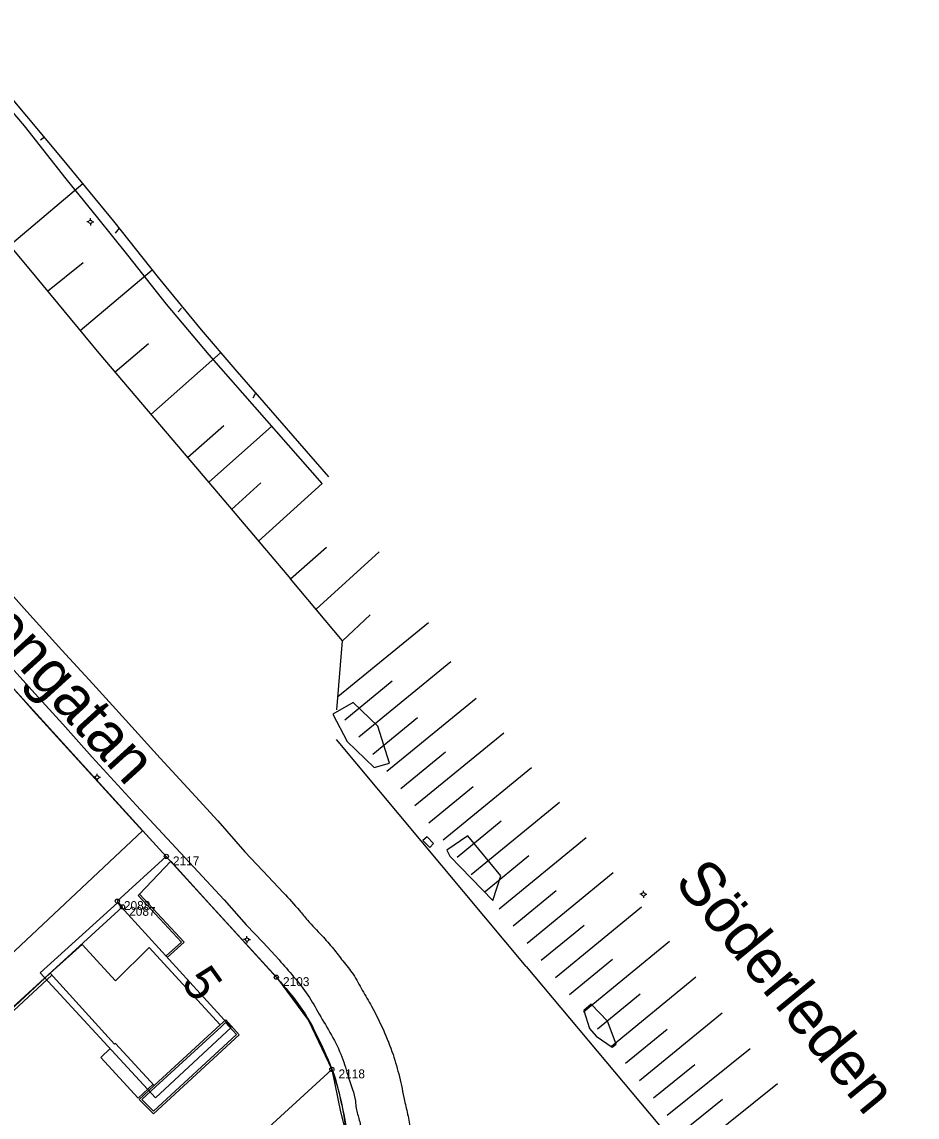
# Model space of a CAD drawing. Extents: x 1517478 to 1518189, y 6494860 to 6495389.
# Drawn here: x 1518083.7 to 1518184.6, y 6495107.4 to 6495230.8 of the extents above; entities that cross this region are included whole.
import ezdxf

# ---------------------------------------------------------------- set-up
doc = ezdxf.new("R2010")
doc.units = 0
for name, color, linetype in [('adress', 7, 'Continuous'), ('bostadshus', 7, 'Continuous'), ('gatunamn', 7, 'Continuous'), ('gc_vag', 7, 'Continuous'), ('grans', 7, 'Continuous'), ('granspunkt', 7, 'Continuous'), ('granspunkt_text', 7, 'Continuous'), ('kvartersgrans', 7, 'Continuous'), ('kvartersgrans_utan_fastgr', 7, 'Continuous'), ('kvartersytor', 7, 'Continuous'), ('planteringskant', 7, 'Continuous'), ('skarmtak', 7, 'Continuous'), ('slant_skraffering', 7, 'Continuous'), ('slantfot', 7, 'Continuous'), ('slantkron', 7, 'Continuous'), ('staket', 7, 'Continuous'), ('stenmur', 7, 'Continuous'), ('stolpe_belysning', 7, 'Continuous'), ('trappa_byggnad', 7, 'Continuous'), ('vagkant', 7, 'Continuous')]:
    doc.layers.add(name, color=color, linetype=linetype)

msp = doc.modelspace()

# ---------------------------------------------------------------- linework, layer by layer
at = {"layer": 'bostadshus'}
msp.add_lwpolyline([(1518086.89, 6495123.66), (1518090.48, 6495126.91), (1518094.25, 6495122.81), (1518098.04, 6495126.57), (1518106.03, 6495117.83), (1518098.62, 6495111.02), (1518094.24, 6495115.73), (1518094.15, 6495115.66), (1518086.88, 6495123.66)], dxfattribs=at)
at = {"layer": 'gc_vag'}
for p, q in [((1518085.02, 6495153.19), (1518097.28, 6495139.69)), ((1518100.47, 6495136.3), (1518096.97, 6495132.58))]:
    msp.add_line(p, q, dxfattribs=at)
for points in [[(1518080.55, 6495158.09), (1518082.73, 6495155.72), (1518085.02, 6495153.19)], [(1518097.3, 6495139.7), (1518079.77, 6495123.29), (1518069.67, 6495123.88)], [(1518100.47, 6495136.3), (1518105.84, 6495130.34), (1518112.4, 6495123.17)]]:
    msp.add_lwpolyline(points, dxfattribs=at)
msp.add_spline([(1518112.4, 6495123.17), (1518115.62, 6495119.07), (1518117.64, 6495115.15), (1518118.65, 6495112.85), (1518119.88, 6495108.19), (1518120.44, 6495104.77), (1518120.39, 6495101.02)], degree=3, dxfattribs=at)
at = {"layer": 'grans'}
for p, q in [((1518094.45, 6495131.78), (1518099.97, 6495136.82)), ((1518099.97, 6495136.82), (1518112.38, 6495123.21)), ((1518095.04, 6495131.13), (1518094.45, 6495131.78)), ((1518079.46, 6495116.91), (1518095.04, 6495131.13)), ((1518118.64, 6495112.82), (1518097.62, 6495093.65))]:
    msp.add_line(p, q, dxfattribs=at)
msp.add_arc((1518089.46, 6495102.3), 31.02, 19.8209, 42.3652, dxfattribs=at)
at = {"layer": 'granspunkt'}
for centre in [(1518099.97, 6495136.82), (1518094.45, 6495131.78), (1518095.04, 6495131.13), (1518112.38, 6495123.21), (1518118.64, 6495112.82)]:
    msp.add_circle(centre, 0.237, dxfattribs=at)
at = {"layer": 'kvartersgrans'}
msp.add_line((1518099.97, 6495136.82), (1518112.38, 6495123.21), dxfattribs=at)
msp.add_arc((1518089.46, 6495102.3), 31.02, 19.8209, 42.3652, dxfattribs=at)
at = {"layer": 'kvartersgrans_utan_fastgr'}
msp.add_line((1518073.64, 6495165.68), (1518099.97, 6495136.82), dxfattribs=at)
msp.add_arc((1518089.47, 6495102.32), 31.01, 350.4256, 19.8012, dxfattribs=at)
at = {"layer": 'kvartersytor'}
msp.add_lwpolyline([(1518073.64, 6495165.68), (1518099.97, 6495136.82), (1518106.17, 6495130.01), (1518112.38, 6495123.21), (1518116.02, 6495118.32), (1518118.64, 6495112.82), (1518119.61, 6495108.06), (1518120.35, 6495105.08)], dxfattribs=at)
at = {"layer": 'planteringskant'}
for points in [[(1518123.4, 6495146.83), (1518125.12, 6495147.31), (1518123.83, 6495151.48), (1518121.03, 6495154.17), (1518118.74, 6495152.84), (1518120.38, 6495149.78), (1518123.4, 6495146.83)], [(1518136.79, 6495131.84), (1518137.69, 6495134.62), (1518133.96, 6495139.12), (1518131.58, 6495137.52), (1518131.95, 6495136.86), (1518136.79, 6495131.84)], [(1518129.67, 6495137.81), (1518130.1, 6495138.28), (1518129.37, 6495139.01), (1518128.91, 6495138.6), (1518129.67, 6495137.81)], [(1518148.45, 6495116.56), (1518150.25, 6495115.31), (1518150.7, 6495115.68), (1518149.7, 6495118.24), (1518147.86, 6495120.16), (1518147.03, 6495119.44), (1518147.69, 6495117.42), (1518148.45, 6495116.56)]]:
    msp.add_lwpolyline(points, dxfattribs=at)
at = {"layer": 'skarmtak'}
for points in [[(1518085.76, 6495123.72), (1518094.48, 6495131.58), (1518107.27, 6495117.56)], [(1518107.27, 6495117.56), (1518098.76, 6495109.61), (1518085.76, 6495123.72)]]:
    msp.add_lwpolyline(points, dxfattribs=at)
at = {"layer": 'slant_skraffering'}
for p, q in [((1518086.24, 6495217.85), (1518085.78, 6495217.53)), ((1518082.3, 6495205.63), (1518090.55, 6495212.65)), ((1518094.66, 6495207.6), (1518094.2, 6495207.05)), ((1518086.57, 6495200.51), (1518090.61, 6495203.72)), ((1518090.27, 6495196.07), (1518098.38, 6495202.9)), ((1518101.7, 6495198.59), (1518101.3, 6495198.19)), ((1518094.19, 6495191.4), (1518097.97, 6495194.59)), ((1518098.24, 6495186.62), (1518106.09, 6495193.55)), ((1518110, 6495188.94), (1518109.72, 6495188.44)), ((1518102.38, 6495181.75), (1518106.46, 6495185.36)), ((1518104.74, 6495178.96), (1518111.87, 6495185.29)), ((1518107.33, 6495175.92), (1518110.62, 6495178.9)), ((1518110.38, 6495172.32), (1518117.53, 6495178.85)), ((1518113.99, 6495168.08), (1518118.04, 6495171.67)), ((1518116.85, 6495164.68), (1518123.96, 6495171.13)), ((1518119.84, 6495161.12), (1518122.96, 6495164.03)), ((1518119.31, 6495154.82), (1518129.53, 6495163.17)), ((1518121.67, 6495150.29), (1518132.04, 6495158.77)), ((1518120.09, 6495152.22), (1518125.44, 6495156.6)), ((1518124.84, 6495146.42), (1518134.91, 6495154.65)), ((1518123.25, 6495148.35), (1518128.3, 6495152.48)), ((1518128, 6495142.55), (1518138.02, 6495150.74)), ((1518126.42, 6495144.48), (1518131.44, 6495148.59)), ((1518131.17, 6495138.68), (1518141.15, 6495146.84)), ((1518129.58, 6495140.61), (1518134.58, 6495144.7)), ((1518134.33, 6495134.8), (1518144.28, 6495142.94)), ((1518132.75, 6495136.74), (1518137.73, 6495140.82)), ((1518137.5, 6495130.93), (1518147.31, 6495138.96)), ((1518135.91, 6495132.87), (1518140.86, 6495136.91)), ((1518140.66, 6495127.06), (1518150.36, 6495134.99)), ((1518139.08, 6495129), (1518143.94, 6495132.98)), ((1518143.83, 6495123.19), (1518153.53, 6495131.13)), ((1518142.24, 6495125.13), (1518147.09, 6495129.09)), ((1518146.99, 6495119.32), (1518156.7, 6495127.26)), ((1518145.41, 6495121.26), (1518150.26, 6495125.23)), ((1518150.16, 6495115.45), (1518159.68, 6495123.24)), ((1518148.57, 6495117.39), (1518153.38, 6495121.32)), ((1518153.32, 6495111.58), (1518162.65, 6495119.21)), ((1518151.74, 6495113.52), (1518156.45, 6495117.37)), ((1518156.45, 6495107.68), (1518165.79, 6495115.18)), ((1518154.89, 6495109.63), (1518159.57, 6495113.39)), ((1518159.58, 6495103.78), (1518168.86, 6495111.24)), ((1518158.02, 6495105.73), (1518162.67, 6495109.47))]:
    msp.add_line(p, q, dxfattribs=at)
at = {"layer": 'slantfot'}
for points in [[(1518092.27, 6495208.77), (1518088.68, 6495213.17), (1518084, 6495219.13), (1518078.82, 6495225.16), (1518074.04, 6495230.84)], [(1518117.53, 6495178.85), (1518104.79, 6495193.34), (1518100, 6495199.05), (1518095.64, 6495204.55), (1518092.27, 6495208.77)]]:
    msp.add_lwpolyline(points, dxfattribs=at)
at = {"layer": 'slantkron'}
msp.add_lwpolyline([(1518119.18, 6495153.33), (1518119.84, 6495161.12), (1518113.99, 6495168.08)], dxfattribs=at)
at = {"layer": 'staket'}
msp.add_line((1518140.54, 6495124.4), (1518119.15, 6495149.98), dxfattribs=at)
for points in [[(1518074.17, 6495215.34), (1518084.47, 6495203.04), (1518092.38, 6495193.53)], [(1518092.38, 6495193.53), (1518106.04, 6495177.43), (1518113.99, 6495168.08)], [(1518140.54, 6495124.4), (1518154.39, 6495107.9), (1518164.18, 6495096.23), (1518184.61, 6495071.96)]]:
    msp.add_lwpolyline(points, dxfattribs=at)
at = {"layer": 'stenmur'}
for p, q in [((1518096.97, 6495132.58), (1518096.82, 6495132.43)), ((1518106.18, 6495117.67), (1518098.77, 6495110.84))]:
    msp.add_line(p, q, dxfattribs=at)
for points in [[(1518096.81, 6495132.43), (1518101.68, 6495127.17), (1518099.94, 6495125.6)], [(1518096.97, 6495132.58), (1518101.99, 6495127.16), (1518100.08, 6495125.44)], [(1518068.15, 6495117.91), (1518079.47, 6495116.8), (1518086.88, 6495123.66)], [(1518068.17, 6495117.6), (1518079.57, 6495116.49), (1518087.08, 6495123.44)], [(1518106.03, 6495117.83), (1518106.68, 6495118.41), (1518108.19, 6495116.73), (1518098.53, 6495107.81), (1518096.9, 6495109.44), (1518098.62, 6495111.01)], [(1518106.18, 6495117.67), (1518106.66, 6495118.1), (1518107.87, 6495116.75), (1518098.53, 6495108.12), (1518097.22, 6495109.43), (1518098.77, 6495110.84)]]:
    msp.add_lwpolyline(points, dxfattribs=at)
at = {"layer": 'stolpe_belysning'}
for p, q in [((1518091.21, 6495208.31), (1518091.01, 6495208.31)), ((1518091.41, 6495208.51), (1518091.41, 6495208.71)), ((1518091.61, 6495208.31), (1518091.81, 6495208.31)), ((1518091.41, 6495208.11), (1518091.41, 6495207.91)), ((1518091.97, 6495145.73), (1518091.77, 6495145.73)), ((1518092.17, 6495145.93), (1518092.17, 6495146.13)), ((1518092.17, 6495145.53), (1518092.17, 6495145.33)), ((1518092.37, 6495145.73), (1518092.57, 6495145.73)), ((1518153.76, 6495132.75), (1518153.76, 6495132.95)), ((1518153.56, 6495132.55), (1518153.36, 6495132.55)), ((1518153.76, 6495132.35), (1518153.76, 6495132.15)), ((1518153.96, 6495132.55), (1518154.16, 6495132.55)), ((1518108.87, 6495127.44), (1518108.67, 6495127.44)), ((1518109.07, 6495127.64), (1518109.07, 6495127.84)), ((1518109.07, 6495127.24), (1518109.07, 6495127.04)), ((1518109.27, 6495127.44), (1518109.47, 6495127.44))]:
    msp.add_line(p, q, dxfattribs=at)
for centre in [(1518091.41, 6495208.31), (1518092.17, 6495145.73), (1518153.76, 6495132.55), (1518109.07, 6495127.44)]:
    msp.add_circle(centre, 0.2, dxfattribs=at)
at = {"layer": 'trappa_byggnad'}
msp.add_lwpolyline([(1518093.65, 6495115.16), (1518092.58, 6495114.18), (1518096.79, 6495109.6), (1518098.49, 6495111.15)], dxfattribs=at)
at = {"layer": 'vagkant'}
for points in [[(1518094.04, 6495208.38), (1518088.29, 6495215.41), (1518082.34, 6495222.5), (1518075.88, 6495230.24)], [(1518118.28, 6495179.58), (1518107.73, 6495191.71), (1518103.93, 6495196.14), (1518099.08, 6495202.03), (1518094.04, 6495208.38)], [(1518069.53, 6495180.63), (1518073.11, 6495176.72), (1518077.69, 6495171.65), (1518081.2, 6495167.8), (1518084.26, 6495164.41)], [(1518077.08, 6495164.11), (1518080.05, 6495160.8), (1518085.2, 6495155.13), (1518088.32, 6495151.7), (1518091.63, 6495148.01)], [(1518084.26, 6495164.41), (1518088.2, 6495160.04), (1518091.69, 6495156.25), (1518095.39, 6495152.22), (1518099.3, 6495147.88)], [(1518091.63, 6495148.01), (1518096.57, 6495142.61), (1518101.57, 6495137.21), (1518106.48, 6495131.94)], [(1518099.3, 6495147.88), (1518102.84, 6495144.03), (1518105.78, 6495140.82), (1518108.84, 6495137.33), (1518110.87, 6495135.18), (1518113.18, 6495132.73)], [(1518106.48, 6495131.94), (1518108.96, 6495129.12), (1518110.9, 6495127.12), (1518112.69, 6495125.15)]]:
    msp.add_lwpolyline(points, dxfattribs=at)
for points in [[(1518113.18, 6495132.73), (1518114.99, 6495130.72), (1518115.9, 6495129.63), (1518117.51, 6495127.9), (1518118.81, 6495126.42), (1518119.87, 6495125.05), (1518121.03, 6495123.54), (1518122.06, 6495121.75), (1518123.12, 6495119.93), (1518124.45, 6495117.26)], [(1518112.69, 6495125.15), (1518114.33, 6495123.27), (1518115.93, 6495121.17), (1518117.21, 6495119.05), (1518118.6, 6495116.69)], [(1518124.44, 6495117.28), (1518125.53, 6495114.5), (1518126.25, 6495111.99), (1518126.83, 6495109.32), (1518127.22, 6495107.56), (1518127.5, 6495105.71), (1518127.5, 6495104.01), (1518127.5, 6495102.5), (1518127.5, 6495100.62)], [(1518118.6, 6495116.69), (1518119.77, 6495114.23), (1518120.52, 6495111.89), (1518121.29, 6495109.23), (1518121.38, 6495108.44), (1518121.73, 6495107.11), (1518121.97, 6495105.66), (1518122.13, 6495103.44), (1518122.04, 6495101.59), (1518121.92, 6495100.31)]]:
    msp.add_spline(points, degree=3, dxfattribs=at)

# ---------------------------------------------------------------- texts
at = {"layer": 'adress'}
msp.add_text('5', height=4, rotation=305.5194, dxfattribs=at).set_placement((1518101.56, 6495122.61))
at = {"layer": 'gatunamn'}
for s, rotation, p in [('Nordengatan', 312.3013, (1518069.51, 6495173.2)), ('Söderleden', 309.3524, (1518157.13, 6495133.88))]:
    msp.add_text(s, height=5, rotation=rotation, dxfattribs=at).set_placement(p)
at = {"layer": 'granspunkt_text'}
for s, p in [('2117', (1518100.72, 6495135.82)), ('2088', (1518095.2, 6495130.78)), ('2087', (1518095.79, 6495130.13)), ('2103', (1518113.13, 6495122.21)), ('2118', (1518119.39, 6495111.82))]:
    msp.add_text(s, height=1, dxfattribs=at).set_placement(p)

doc.saveas('drawing.dxf')
